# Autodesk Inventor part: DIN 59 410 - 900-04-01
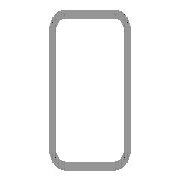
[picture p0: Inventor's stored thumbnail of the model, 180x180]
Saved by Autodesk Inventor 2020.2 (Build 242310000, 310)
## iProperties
Manager: www.cadconsulting.pl
Company: Fabian Stasiak CAD Consulting
Created: 2015-02
Part Number: DIN 59 410 - 900-04-01
Material: Stal, miękka
Description: Rurki stalowe o przekroju prostokątnym formowane na gorąco
Document SubType Name: Modellieren
Standard: DIN 59 410
Designer: F.Stasiak
Standards Organization: DIN
Language: pl-PL
Size Designation: 100x50x4.5-1680
Categories: <MemberInstance><Categories><Category DisplayName="Kształtowniki konstrukcyjne" InternalName="089c4875-fa83-4c05-b084-43b9cc11f5ed" Mnemonic="GRDR"><CategoryPar
Stock Number: 100x50x4.5
Density: 7.85 g/cm^3
Appearance: Częściowo polerowany
Catalog Web Link: www.expertbooks.pl
IsCustomPart: 1
G_L: 1800,000 mm
Author: F.Stasiak
Subject: Zbiór ćwiczeń. Autodesk Inventor 2020. Kurs Professional
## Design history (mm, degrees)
node "Płaszczyzna początkowa"
node "Płaszczyzna końcowa"
sketch "Szkic1"
  geometry: L1 (-20, 60)-(20, 60); L2 (30, 50)-(30, -50); L3 (20, -60)-(-20, -60); L4 (-30, -50)-(-30, 50); L5 (-44.61, 0)-(44.61, 0) reference; L6 (0, -86.61)-(0, 86.61) reference; L7 (-20, 55)-(20, 55); L8 (25, 50)-(25, -50); L9 (20, -55)-(-20, -55); L10 (-25, -50)-(-25, 50); A1 r 10 centre (-20, 50) between (-20, 60) and (-30, 50); A2 r 10 centre (20, 50) between (30, 50) and (20, 60); A3 r 10 centre (20, -50) between (20, -60) and (30, -50); A4 r 10 centre (-20, -50) between (-30, -50) and (-20, -60); A5 r 5 centre (-20, 50) between (-20, 55) and (-25, 50); A6 r 5 centre (20, 50) between (25, 50) and (20, 55); A7 r 5 centre (20, -50) between (20, -55) and (25, -50); A8 r 5 centre (-20, -50) between (-25, -50) and (-20, -55); 3 further points
  constraints: 16 end point, 16 point on circle, 8 centre point, 8 tangent, 6 point on line, 4 parallel, 3 equal radius, 2 perpendicular, 1 horizontal, 7 other
  dimensions: "b" = 60 distance of point (-30, 60) point (30, 60); "ParH" = 120 distance of point (30, 60) point (30, -60); "msp_r" = 10 radius of A1 (= 2 x ParT); "d8" = 30 distance between parallel lines of L4 L6 (= 0.5 x b); "d9" = 60 distance between parallel lines of L5 L1 (= 0.5 x ParH); "d10" = 5 distance between parallel lines of L4 L10 (= ParT)
extrude "Bryła" new body sketch "Szkic1" taper "d4" = 0 deg; stored distance "NLG" = 10
node "Driven Length"
  sketch "Sketch2"
    geometry: L1 (0, 0)-(10, 0) reference
    constraints: 2 end point, 1 horizontal
  workplane "Work Plane3"
  sketch "Sketch3"
    geometry: L1 (-2, 0)-(12, 0) reference; L2 (-2, 1800)-(12, 1800) reference
    dimensions: "d14" = 1800 distance between parallel lines of L1 L2 (derived)
sketch "Szkic4"
  geometry: L1 (0, 100)-(0, 0) reference; L2 (1800, 100)-(1800, 0) reference; L3 (0, 50)-(1800, 50); 3 further points
  constraints: 2 end point, 2 midpoint, 2 point on line, 1 horizontal
  dimensions: "d15" = 60 distance from line of L1 point (60, 50); "d16" = 60 distance from line of L2 point (1740, 50)
hole "Otwór1" sketch "Szkic4" at (900, 50), (1740, 50), (60, 50) diameter "d17" = 50; stored, may be unused: countersink angle "d21" = 90 deg, drill point angle "d23" = 118 deg; dims "d18" = 6, "d19" = 4, "d20" = 2, "d22" = 8
sketch "Szkic5"
  geometry: L1 (0, 10)-(1800, 10) reference; L2 (0, -110)-(1800, -110) reference; L3 (63.629, 10)-(10, -35); L4 (10, -35)-(10, -65); L5 (10, -65)-(63.629, -110); L6 (0, 10)-(0, -110); C1 r 25 at (60, -50) reference; 1 further point
  constraints: 8 end point, 2 point on line, 1 equal length, 1 perpendicular, 1 vertical, 1 vertical alignment
  dimensions: "d24" = 50 distance from line of C1.centre L4; "d25" = 130 deg angle of L3 L4; "d26" = 30 distance of L3.end L4.end
extrude "Wyciągnięcie proste2" cut sketch "Szkic5" extent not by distance; stored distance "d27" = 10; taper "d28" = 0 deg
node "Płaszczyzna konstrukcyjna5"
  node "Oś konstrukcyjna1"
mirror "Odbicie lustrzane1"
body "Solid1"
other parameters: "ParT" = 5, "G_OFFSET_START" = 0 [user parameter; used in 1 equation term], "G_OFFSET_END" = 0 [user parameter; used in 1 equation term], "d11" = 0 (computed from G_OFFSET_START), "G_L" = 1800 (= d14) [user parameter], "d13" = 90 deg, "d29" = 0
